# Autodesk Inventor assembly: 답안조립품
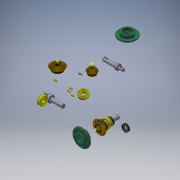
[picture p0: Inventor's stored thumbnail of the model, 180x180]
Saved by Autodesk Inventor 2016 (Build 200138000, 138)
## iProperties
Created: 2019-08
Part Number: 답안조립품
Material: 일반
Document SubType Name: Assembly
Designer: user
Author: user
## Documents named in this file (16)
- D:\490823V1012\답안조립품.iam
- D:\490823V1012\본체.ipt
- D:\490823V1012\메인 베벨기어.ipt
- D:\490823V1012\메인 축.ipt
- 메인 축.ipt
- D:\490823V1012\베어링 6203.ipt
- D:\490823V1012\볼트 M4.ipt
- 볼트 M4.ipt
- D:\490823V1012\서브 베벨기어.ipt
- D:\490823V1012\서브 축.ipt
- 서브 축.ipt
- D:\490823V1012\오일 실.ipt
- 오일 실.ipt
- D:\490823V1012\커버.ipt
- D:\490823V1012\키 4x4.ipt
- D:\490823V1012\키 5x5.ipt
